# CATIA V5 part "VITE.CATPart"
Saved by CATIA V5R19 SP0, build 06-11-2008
Part number: VITE
Bounding box of the stored display mesh (mm): x -12.424 to -5.424, y 1.211 to 8.189, z 53.327 to 61.701
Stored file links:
  C:\Users\sisca\Desktop\HELTEC_CASE\VITE.CATPart
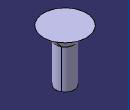
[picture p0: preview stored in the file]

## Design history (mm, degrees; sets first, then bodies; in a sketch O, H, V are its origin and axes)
Set1
  Plane1: stored without definition
Body1 (main body)
  Sketch1 on Plane1, origin (0, 4.7002, 0), H (-1, 0, 0), V (0, 0, 1)
    point P1 (7.4241, 59.7012)
    line L1 (7.4241, 59.7012) -> (7.4241, 53.3271)
    line L2 (7.4241, 53.3271) -> (8.9241, 53.3271)
    line L3 (8.9241, 53.3271) -> (8.9241, 61.7012)
    line L4 (8.9241, 61.7012) -> (5.4241, 61.7012)
    line L5 (5.4241, 61.7012) -> (7.4241, 59.7012)
    distance L3 L1 = 1.5
    length L4 = 3.5
    distance L4 P1 = 2
    vertical: L1 V, L3 V
    horizontal: L2 H, L4 H
  Shaft1: profile Sketch1, axis Sketch1.L3, angle 360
